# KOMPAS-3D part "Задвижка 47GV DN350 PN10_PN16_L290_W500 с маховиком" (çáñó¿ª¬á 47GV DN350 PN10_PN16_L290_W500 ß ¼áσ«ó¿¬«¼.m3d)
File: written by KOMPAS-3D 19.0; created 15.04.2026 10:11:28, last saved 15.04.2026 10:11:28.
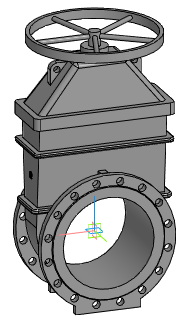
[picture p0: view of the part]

Document properties: Автор: Евгений; Полное имя файла: Z:\3.Личные\kachalov\3d для проектировщиков\2.1 Тип 47GV, 47GV.Z\Задвижка 47GV_DN40-DN600\stp_Задвижка 47GV\Задвижка 47GV DN350 PN10_PN16_L290_W500 с маховиком.m3d

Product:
- Part/product: Задвижка 47GV DN350 PN10_PN16_L290_W500 с маховиком

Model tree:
1. Операция без истории:1  (labels: Задвижка 47GV DN350 PN10_PN16_L290_W500 с маховиком)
